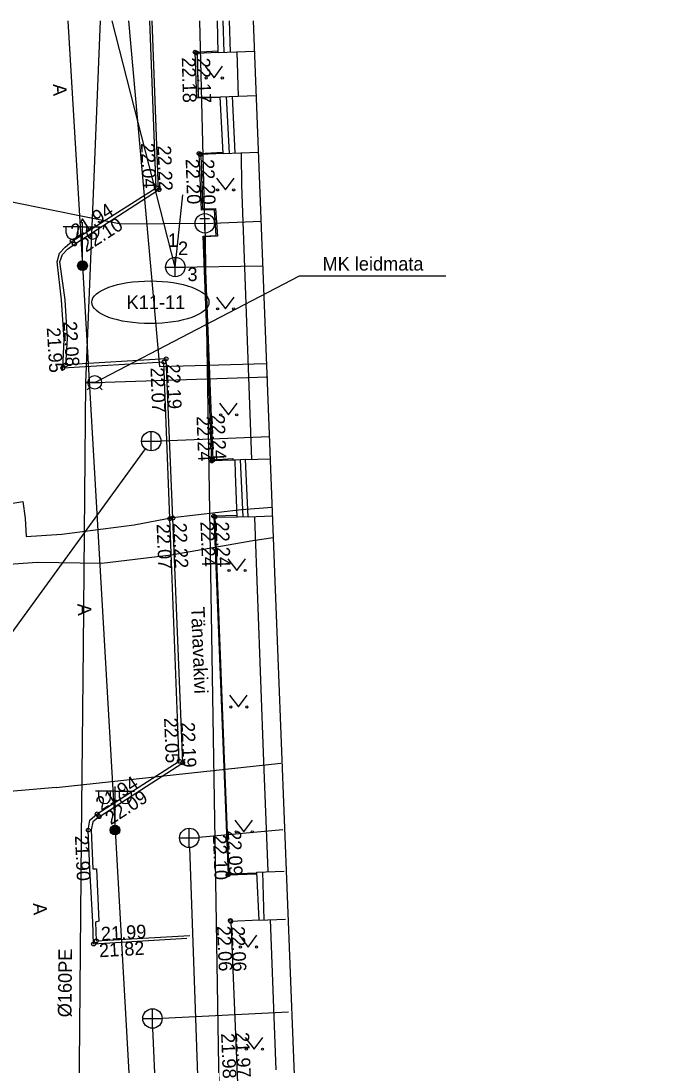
# Model space of a CAD drawing. Extents: x 714038 to 714279, y 6589845 to 6590041.
# Drawn here: x 714162.2 to 714195.2, y 6589987.2 to 6590041 of the extents above; entities that cross this region are included whole.
import ezdxf

# ---------------------------------------------------------------- set-up
doc = ezdxf.new("R2010")
doc.units = 0
for name, color, linetype in [('HALJASTUS', 7, 'Continuous'), ('HOONE', 7, 'Continuous'), ('HOONEDET', 7, 'Continuous'), ('KAEVU_NR', 7, 'Continuous'), ('KKAEV', 7, 'Continuous'), ('KORGUS', 7, 'Continuous'), ('KTRASS', 7, 'Continuous'), ('MPKAABEL', 7, 'Continuous'), ('POST', 7, 'Continuous'), ('SITRASS', 7, 'Continuous'), ('SKKAEV', 7, 'Continuous'), ('SKTRASS', 7, 'Continuous'), ('TEE', 7, 'Continuous'), ('TKAEV', 7, 'Continuous'), ('TORU NR', 7, 'Continuous'), ('TTRASS', 7, 'Continuous'), ('VKAEV', 7, 'Continuous'), ('VTRASS', 7, 'Continuous')]:
    doc.layers.add(name, color=color, linetype=linetype)

msp = doc.modelspace()

# ---------------------------------------------------------------- linework, layer by layer
at = {"layer": 'HALJASTUS'}
for p, q in [((714171.664, 6590038.632), (714172.128, 6590038.025)), ((714172.128, 6590038.025), (714172.573, 6590038.632)), ((714172.249, 6590032.861), (714172.713, 6590032.254)), ((714172.713, 6590032.254), (714173.158, 6590032.861)), ((714172.249, 6590026.731), (714172.713, 6590026.124)), ((714172.713, 6590026.124), (714173.158, 6590026.731)), ((714172.404, 6590021.268), (714172.868, 6590020.661)), ((714172.868, 6590020.661), (714173.313, 6590021.268)), ((714172.838, 6590013.246), (714173.301, 6590012.64)), ((714173.301, 6590012.64), (714173.747, 6590013.246)), ((714172.93, 6590006.214), (714173.394, 6590005.607)), ((714173.394, 6590005.607), (714173.839, 6590006.214)), ((714173.207, 6589999.776), (714173.671, 6589999.169)), ((714173.671, 6589999.169), (714174.116, 6589999.776)), ((714173.425, 6589993.843), (714173.888, 6589993.236)), ((714173.888, 6589993.236), (714174.334, 6589993.843)), ((714173.733, 6589988.575), (714174.196, 6589987.969)), ((714174.196, 6589987.969), (714174.642, 6589988.575))]:
    msp.add_line(p, q, dxfattribs=at)
for centre in [(714171.727, 6590038.025), (714172.555, 6590038.025), (714172.312, 6590032.254), (714173.141, 6590032.254), (714172.312, 6590026.124), (714173.141, 6590026.124), (714172.467, 6590020.661), (714173.295, 6590020.661), (714172.9, 6590012.64), (714173.729, 6590012.64), (714172.993, 6590005.607), (714173.821, 6590005.607), (714173.27, 6589999.169), (714174.099, 6589999.169), (714173.487, 6589993.236), (714174.316, 6589993.236), (714173.795, 6589987.969), (714174.624, 6589987.969)]:
    msp.add_circle(centre, 0.055, dxfattribs=at)
at = {"layer": 'HOONE'}
msp.add_lwpolyline([(714174.151, 6590040.965), (714175.285, 6590011.657), (714176.665, 6589976.107), (714220.25, 6589977.79), (714221.11, 6589977.83), (714221.8, 6589965.63), (714240.53, 6589966.47), (714239.93, 6589984.45), (714258.589, 6589985.264), (714256.524, 6590035.954)], dxfattribs=at)
at = {"layer": 'HOONEDET'}
for points in [[(714173.382, 6590037.089), (714173.321, 6590039.373)], [(714174.081, 6590018.367), (714173.556, 6590032.502), (714173.537, 6590034.096), (714173.536, 6590034.161)], [(714174.92, 6589997.144), (714174.697, 6590002.804), (714174.23, 6590015.37)], [(714175.018, 6589994.649), (714175.312, 6589986.916)]]:
    msp.add_lwpolyline(points, dxfattribs=at)
at = {"layer": 'KAEVU_NR'}
msp.add_ellipse((714168.848, 6590026.463), major_axis=(-3.02, 0), ratio=0.364056, dxfattribs=at)
at = {"layer": 'KKAEV'}
for p, q in [((714170.132, 6590027.781), (714170.132, 6590028.781)), ((714169.632, 6590028.281), (714170.632, 6590028.281)), ((714170.851, 6589998.362), (714170.851, 6589999.362)), ((714170.351, 6589998.862), (714171.351, 6589998.862))]:
    msp.add_line(p, q, dxfattribs=at)
for centre in [(714170.132, 6590028.281), (714170.851, 6589998.862)]:
    msp.add_circle(centre, 0.5, dxfattribs=at)
at = {"layer": 'KORGUS'}
for centre in [(714171.16, 6590039.353), (714171.223, 6590039.316), (714171.356, 6590034.129), (714171.424, 6590034.085), (714169.155, 6590032.358), (714169.301, 6590032.273), (714164.821, 6590029.619), (714164.936, 6590029.465), (714164.336, 6590023.075), (714164.493, 6590023.242), (714169.541, 6590023.382), (714169.662, 6590023.547), (714172.016, 6590018.287), (714172.069, 6590018.336), (714169.856, 6590015.318), (714170.004, 6590015.344), (714172.113, 6590015.444), (714172.181, 6590015.406), (714170.34, 6590002.809), (714170.515, 6590002.731), (714166.105, 6590000.096), (714166.211, 6589999.954), (714165.647, 6589999.259), (714172.849, 6589996.961), (714172.905, 6589997.015), (714172.97, 6589994.601), (714172.996, 6589994.554), (714166.062, 6589993.553), (714165.923, 6589993.392)]:
    msp.add_circle(centre, 0.1, dxfattribs=at)
at = {"layer": 'KTRASS'}
for points in [[(714170.132, 6590028.281), (714166.872, 6590040.965)], [(714170.132, 6590028.281), (714170.518, 6590031.995)], [(714170.132, 6590028.281), (714174.65, 6590028.35)], [(714171.349, 6589998.906), (714175.672, 6589999.288)], [(714170.858, 6589998.362), (714171.462, 6589981.232)]]:
    msp.add_lwpolyline(points, dxfattribs=at)
at = {"layer": 'MPKAABEL'}
for points in [[(714164.593, 6590040.965), (714165.351, 6590028.35), (714167.029, 6589999.261)], [(714167.727, 6590040.965), (714169.31, 6590023.16), (714174.82, 6590023.3)], [(714167.029, 6589999.261), (714167.805, 6589985.535), (714167.801, 6589985.524), (714168.701, 6589969.69), (714168.856, 6589964.517), (714181.003, 6589963.765), (714182.873, 6589963.649), (714187.834, 6589963.342), (714201.122, 6589963.986), (714214.138, 6589964.636), (714217.634, 6589964.759), (714217.843, 6589958.743), (714218.335, 6589947.958), (714218.782, 6589937.076), (714219.871, 6589937.206), (714226.57, 6589937.936), (714228.214, 6589938.132), (714236.763, 6589938.683), (714246.845, 6589940.926), (714247.938, 6589921.303)]]:
    msp.add_lwpolyline(points, dxfattribs=at)
at = {"layer": 'POST'}
for p, q in [((714165.351, 6590030.35), (714164.351, 6590030.35)), ((714164.512, 6590030.029), (714164.512, 6590030.35)), ((714165.124, 6590030.029), (714165.124, 6590030.35)), ((714165.351, 6590028.6), (714165.351, 6590030.6)), ((714165.351, 6590030.35), (714166.351, 6590030.35)), ((714165.578, 6590030.029), (714165.578, 6590030.35)), ((714166.19, 6590030.029), (714166.19, 6590030.35)), ((714167.029, 6590001.261), (714166.029, 6590001.261)), ((714166.19, 6590000.94), (714166.19, 6590001.261)), ((714166.802, 6590000.94), (714166.802, 6590001.261)), ((714167.029, 6589999.511), (714167.029, 6590001.511)), ((714167.029, 6590001.261), (714168.029, 6590001.261)), ((714167.256, 6590000.94), (714167.256, 6590001.261)), ((714167.868, 6590000.94), (714167.868, 6590001.261))]:
    msp.add_line(p, q, dxfattribs=at)
for centre, radius in [((714165.351, 6590028.35), 0.25), ((714165.351, 6590028.35), 0.225), ((714165.351, 6590028.35), 0.2), ((714165.351, 6590028.35), 0.175), ((714165.351, 6590028.35), 0.15), ((714165.351, 6590028.35), 0.125), ((714165.351, 6590028.35), 0.1), ((714165.351, 6590028.35), 0.075), ((714165.351, 6590028.35), 0.05), ((714165.351, 6590028.35), 0.025), ((714167.029, 6589999.261), 0.25), ((714167.029, 6589999.261), 0.225), ((714167.029, 6589999.261), 0.2), ((714167.029, 6589999.261), 0.175), ((714167.029, 6589999.261), 0.15), ((714167.029, 6589999.261), 0.125), ((714167.029, 6589999.261), 0.1), ((714167.029, 6589999.261), 0.075), ((714167.029, 6589999.261), 0.05), ((714167.029, 6589999.261), 0.025)]:
    msp.add_circle(centre, radius, dxfattribs=at)
for centre in [(714164.818, 6590030.029), (714165.884, 6590030.029), (714166.496, 6590000.94), (714167.562, 6590000.94)]:
    msp.add_arc(centre, 0.306, 180, 0, dxfattribs=at)
at = {"layer": 'SITRASS'}
for points in [[(714153.969, 6590019.777), (714155.294, 6590019.865), (714156.05, 6590019.166), (714156.398, 6590018.084), (714156.778, 6590016.734), (714157.468, 6590016.238), (714159.581, 6590016.127), (714160.804, 6590015.95), (714162.282, 6590016.195), (714162.403, 6590015.338), (714162.44, 6590014.401), (714164.294, 6590014.521), (714168.017, 6590014.987), (714169.99, 6590015.378), (714173.537, 6590015.781), (714175.12, 6590015.912)], [(714154.374, 6590012.596), (714159.865, 6590012.844), (714163.01, 6590013.069), (714166.345, 6590013.02), (714169.914, 6590013.444), (714174.135, 6590014.18), (714175.181, 6590014.334)]]:
    msp.add_lwpolyline(points, dxfattribs=at)
at = {"layer": 'SKKAEV'}
for p, q in [((714168.894, 6590018.807), (714168.894, 6590019.807)), ((714168.394, 6590019.307), (714169.394, 6590019.307)), ((714168.957, 6589989.053), (714168.957, 6589990.053)), ((714168.457, 6589989.553), (714169.457, 6589989.553))]:
    msp.add_line(p, q, dxfattribs=at)
for centre in [(714168.894, 6590019.307), (714168.957, 6589989.553)]:
    msp.add_circle(centre, 0.5, dxfattribs=at)
at = {"layer": 'SKTRASS'}
for points in [[(714169.394, 6590019.326), (714174.98, 6590019.543)], [(714158.983, 6590005.685), (714168.6, 6590018.903)], [(714169.456, 6589989.578), (714175.965, 6589989.901)], [(714169.079, 6589986.737), (714168.979, 6589989.053)]]:
    msp.add_lwpolyline(points, dxfattribs=at)
at = {"layer": 'TEE'}
for points in [[(714166.105, 6590000.096), (714170.34, 6590002.809), (714169.856, 6590015.318), (714169.541, 6590023.382), (714164.336, 6590023.075), (714164.401, 6590024.553), (714164.267, 6590026.585), (714164.041, 6590028.555), (714164.168, 6590028.997), (714164.456, 6590029.31), (714164.821, 6590029.619), (714169.155, 6590032.358), (714168.812, 6590040.965)], [(714166.211, 6589999.954), (714170.515, 6590002.731), (714170.004, 6590015.344), (714169.662, 6590023.547), (714164.493, 6590023.242), (714164.574, 6590024.574), (714164.451, 6590026.59), (714164.191, 6590028.543), (714164.329, 6590028.933), (714164.571, 6590029.208), (714164.936, 6590029.465), (714169.269, 6590032.251), (714168.935, 6590040.965)], [(714172.343, 6590039.335), (714172.306, 6590040.965)], [(714172.653, 6590039.347), (714172.597, 6590040.965)], [(714172.913, 6590040.965), (714172.955, 6590039.359)], [(714172.468, 6590037.024), (714171.243, 6590036.989), (714171.16, 6590039.353), (714172.322, 6590039.414)], [(714172.343, 6590039.335), (714171.252, 6590039.278), (714171.309, 6590037.028), (714172.451, 6590037.053)], [(714172.343, 6590039.335), (714174.211, 6590039.407)], [(714172.451, 6590037.053), (714174.299, 6590037.125)], [(714172.601, 6590034.124), (714172.451, 6590037.053)], [(714172.918, 6590034.136), (714172.77, 6590037.065)], [(714173.064, 6590037.077), (714173.205, 6590034.148)], [(714173.209, 6590018.334), (714173.09, 6590018.326), (714172.016, 6590018.287), (714171.565, 6590029.877), (714172.233, 6590029.909), (714172.147, 6590031.234), (714171.482, 6590031.209), (714171.356, 6590034.129), (714172.587, 6590034.192), (714172.597, 6590034.193)], [(714172.601, 6590034.124), (714171.444, 6590034.086), (714171.54, 6590031.282), (714172.196, 6590031.296), (714172.302, 6590029.863), (714171.612, 6590029.834), (714172.069, 6590018.336), (714173.097, 6590018.41), (714173.103, 6590018.327)], [(714172.601, 6590034.124), (714174.416, 6590034.195)], [(714173.754, 6590018.354), (714173.209, 6590018.334)], [(714173.315, 6590015.395), (714173.234, 6590017.632), (714173.209, 6590018.334)], [(714173.482, 6590018.344), (714173.613, 6590015.409)], [(714173.754, 6590018.354), (714175.024, 6590018.403)], [(714173.883, 6590015.411), (714173.754, 6590018.354)], [(714173.321, 6590015.478), (714172.113, 6590015.444), (714172.613, 6590002.932), (714172.849, 6589996.961), (714174.335, 6589997.012)], [(714174.333, 6589997.043), (714172.906, 6589996.998), (714172.673, 6590002.936), (714172.181, 6590015.406), (714173.318, 6590015.388)], [(714173.883, 6590015.411), (714173.315, 6590015.395)], [(714173.883, 6590015.411), (714175.143, 6590015.458)], [(714170.724, 6589993.669), (714165.923, 6589993.392), (714165.879, 6589994.528), (714165.737, 6589997.266), (714165.647, 6589999.259), (714165.732, 6589999.766), (714166.105, 6590000.096)], [(714166.211, 6589999.954), (714165.881, 6589999.68), (714165.79, 6589999.273), (714165.876, 6589997.259), (714166.066, 6589997.258), (714166.186, 6589994.569), (714166.016, 6589994.514), (714166.062, 6589993.553), (714170.888, 6589993.83)], [(714174.451, 6589994.627), (714174.331, 6589997.095), (714175.739, 6589997.149)], [(714174.712, 6589994.637), (714174.648, 6589997.107)], [(714174.451, 6589994.627), (714172.996, 6589994.554), (714173.376, 6589985.388), (714173.524, 6589985.404)], [(714174.451, 6589994.627), (714175.816, 6589994.68)]]:
    msp.add_lwpolyline(points, dxfattribs=at)
at = {"layer": 'TKAEV'}
for p, q in [((714171.403, 6590030.781), (714171.903, 6590030.781)), ((714171.653, 6590030.181), (714171.653, 6590030.781))]:
    msp.add_line(p, q, dxfattribs=at)
msp.add_circle((714171.653, 6590030.531), 0.5, dxfattribs=at)
at = {"layer": 'TTRASS'}
for points in [[(714171.653, 6590030.531), (714171.4, 6590040.965)], [(714171.653, 6590030.531), (714167.33, 6590030.49), (714156.069, 6590032.753), (714156.51, 6590034.95), (714153.78, 6590035.59), (714153.09, 6590033.35), (714134.271, 6590037.038)], [(714171.653, 6590030.531), (714174.55, 6590030.643)], [(714171.653, 6590030.531), (714172.374, 6589986.01), (714172.85, 6589973.48), (714175.36, 6589973.53), (714175.475, 6589969.349)]]:
    msp.add_lwpolyline(points, dxfattribs=at)
at = {"layer": 'VKAEV'}
for p, q in [((714165.737, 6590022.087), (714165.597, 6590021.948)), ((714165.737, 6590022.087), (714165.597, 6590021.948)), ((714165.634, 6590022.335), (714166.334, 6590022.335)), ((714165.634, 6590022.335), (714166.334, 6590022.335)), ((714166.232, 6590022.087), (714166.372, 6590021.948)), ((714166.232, 6590022.087), (714166.372, 6590021.948))]:
    msp.add_line(p, q, dxfattribs=at)
msp.add_lwpolyline([(714165.984, 6590022.335), (714176.527, 6590027.82), (714184.077, 6590027.82)], dxfattribs=at)
msp.add_circle((714165.984, 6590022.335), 0.35, dxfattribs=at)
msp.add_circle((714165.984, 6590022.335), 0.35, dxfattribs=at)
at = {"layer": 'VTRASS'}
msp.add_line((714165.984, 6590022.335), (714165.506, 6590022.329), dxfattribs=at)
for points in [[(714166.254, 6590040.965), (714165.506, 6590022.329), (714165.378, 6590008.723), (714165.284, 6589998.807), (714165.141, 6589983.322), (714160.198, 6589966.563), (714155.909, 6589952.01), (714153.798, 6589949.498)], [(714165.506, 6590022.329), (714165.984, 6590022.335), (714174.898, 6590022.617)], [(714163.993, 6590001.465), (714175.565, 6590002.716)], [(714163.993, 6590001.465), (714155.047, 6590000.681)]]:
    msp.add_lwpolyline(points, dxfattribs=at)

# ---------------------------------------------------------------- texts
at = {"layer": 'KAEVU_NR'}
msp.add_text('K11-11', height=0.7, dxfattribs=at).set_placement((714167.625, 6590026.113))
at = {"layer": 'KORGUS'}
for s, rotation, p in [(' 22.18', 271.4534, (714170.46, 6590039.335)), (' 22.17', 271.4534, (714171.223, 6590039.316)), (' 22.04', 272.2808, (714168.352, 6590034.918)), (' 22.22', 272.2808, (714169.201, 6590034.791)), (' 22.20', 271.9613, (714170.656, 6590034.105)), (' 22.20', 271.9613, (714171.424, 6590034.085)), (' 21.94', 32.7399, (714164.821, 6590029.619)), (' 22.10', 32.7399, (714165.315, 6590028.876)), (' 22.08', 273.4914, (714164.342, 6590025.722)), (' 21.95', 273.4914, (714163.492, 6590025.408)), (' 22.19', 272.237, (714169.662, 6590023.547)), (' 22.07', 272.237, (714168.842, 6590023.355)), (' 22.24', 272.2761, (714171.214, 6590020.847)), (' 22.24', 272.2761, (714171.966, 6590020.924)), (' 22.22', 272.32, (714170.004, 6590015.344)), (' 22.24', 272.2594, (714171.414, 6590015.416)), (' 22.24', 272.2594, (714172.181, 6590015.406)), (' 22.07', 272.32, (714169.157, 6590015.29)), (' 22.05', 272.2158, (714169.543, 6590005.3)), (' 22.19', 272.2158, (714170.424, 6590005.074)), (' 21.94', 32.8307, (714166.105, 6590000.096)), (' 22.09', 32.8307, (714166.591, 6589999.366)), (' 21.90', 272.5856, (714164.948, 6589999.227)), (' 22.10', 272.2471, (714172.058, 6589999.277)), (' 22.09', 272.2471, (714172.808, 6589999.498)), (' 21.99', 3.2868, (714166.062, 6589993.553)), (' 22.06', 272.3741, (714172.271, 6589994.572)), (' 22.06', 272.3741, (714172.996, 6589994.554)), (' 21.82', 3.2868, (714165.963, 6589992.693)), (' 21.98', 272.3741, (714172.479, 6589989.04)), (' 21.97', 272.3741, (714173.222, 6589989.093))]:
    msp.add_text(s, height=0.7, rotation=rotation, dxfattribs=at).set_placement(p)
at = {"layer": 'TEE'}
for s, rotation, p in [('A', 272.2808, (714163.827, 6590037.709)), ('A', 272.8709, (714165.089, 6590010.925)), ('Tänavakivi', 272.32, (714170.942, 6590010.749)), ('A', 273.0002, (714162.799, 6589995.493))]:
    msp.add_text(s, height=0.7, rotation=rotation, dxfattribs=at).set_placement(p)
at = {"layer": 'TORU NR'}
for s, p in [('1', (714169.752, 6590029.314)), ('2', (714170.273, 6590028.894)), ('3', (714170.759, 6590027.556))]:
    msp.add_text(s, height=0.7, dxfattribs=at).set_placement(p)
at = {"layer": 'VKAEV'}
msp.add_text('MK leidmata', height=0.7, dxfattribs=at).set_placement((714177.718, 6590028.098))
at = {"layer": 'VTRASS'}
msp.add_text('%%C160PE', height=0.7, rotation=89.4697, dxfattribs=at).set_placement((714164.78, 6589989.613))

doc.saveas('drawing.dxf')
